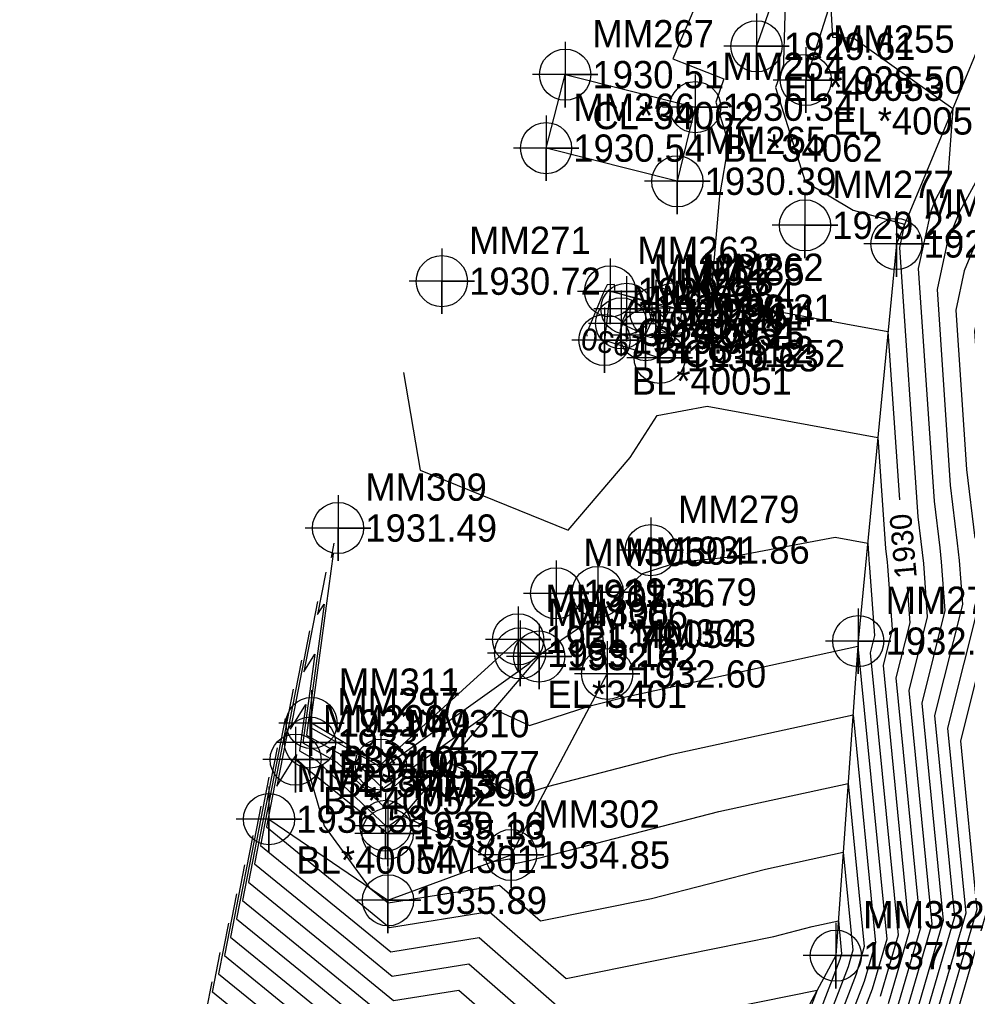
# Model space of a CAD drawing. Extents: x 1004378 to 1005103, y 553854 to 554288.
# Drawn here: x 1004892.9 to 1004979.8, y 554119.4 to 554208.9 of the extents above; entities that cross this region are included whole.
import ezdxf

# ---------------------------------------------------------------- set-up
doc = ezdxf.new("R2010")
doc.units = 0
for name, color, linetype in [('DTM Contours Major', 7, 'Continuous'), ('DTM Contours Major Text', 7, 'Continuous'), ('DTM Contours Minor', 7, 'Continuous'), ('Exist Building Cogo Elevation', 7, 'Continuous'), ('Exist Building Cogo Number', 7, 'Continuous'), ('Exist Building Cogo Point CELL', 7, 'Continuous'), ('Exist DTM Breakline', 7, 'Continuous'), ('Exist DTM Breakline Cogo Comment', 7, 'Continuous'), ('Exist DTM Breakline Cogo Elevation', 7, 'Continuous'), ('Exist DTM Breakline Cogo Number', 7, 'Continuous'), ('Exist DTM Breakline Cogo Point CELL', 7, 'Continuous'), ('Exist DTM Regular Point CELL', 7, 'Continuous'), ('Exist DTM Regular Point Cogo Elevation', 7, 'Continuous'), ('Exist DTM Regular Point Cogo Number', 7, 'Continuous'), ('Exist Other Culture Area Outline Cogo Comment', 7, 'Continuous'), ('Exist Other Culture Area Outline Cogo Elevation', 7, 'Continuous'), ('Exist Other Culture Area Outline Cogo Number', 7, 'Continuous'), ('Exist Other Culture Area Outline Cogo Point CELL', 7, 'Continuous'), ('Exist Structure Minor Drop Inlet Cogo Comment', 7, 'Continuous'), ('Exist Structure Minor Drop Inlet Cogo Elevation', 7, 'Continuous'), ('Exist Structure Minor Drop Inlet Cogo Number', 7, 'Continuous'), ('Exist Structure Minor Drop Inlet Cogo Point CELL', 7, 'Continuous')]:
    doc.layers.add(name, color=color, linetype=linetype)

msp = doc.modelspace()

# ---------------------------------------------------------------- linework, layer by layer
at = {"layer": 'DTM Contours Major'}
for points in [[(1004959.718, 554247.837), (1004956.604, 554227.189), (1004954.914, 554210.3), (1004952.827, 554205.351), (1004957.486, 554203.505), (1004956.747, 554201.367), (1004957.928, 554197.612), (1004957.091, 554192.78), (1004956.399, 554184.65), (1004957.552, 554183.351), (1004960.987, 554182.443), (1004972.543, 554180.34), (1004973.586, 554164.908)], [(1004988.055, 554197.353), (1004983.519, 554189.087), (1004981.07, 554183.147), (1004980.472, 554180.378), (1004981.231, 554169.159), (1004982.126, 554161.833), (1004982.368, 554159.624), (1004982.603, 554156.477), (1004979.182, 554142.834), (1004980.705, 554127.374), (1004976.99, 554114.65), (1004972.242, 554102.28), (1004972.017, 554101.096)], [(1004952.565, 554182.386), (1004951.57, 554182.721), (1004947.519, 554183.91), (1004947.453, 554184.657), (1004946.803, 554184.619), (1004946.533, 554184.06), (1004944.903, 554180.156), (1004944.942, 554179.927)], [(1004951.036, 554178.96), (1004952.198, 554181.759), (1004952.565, 554182.386)], [(1004974.291, 554156.941), (1004974.539, 554153.633), (1004973.275, 554148.595), (1004975.533, 554125.683), (1004973.303, 554118.045), (1004966.649, 554100.709), (1004964.833, 554091.127), (1004964.446, 554090.268), (1004962.705, 554079.148), (1004961.826, 554075.049), (1004962.449, 554069.829), (1004964.566, 554059.674), (1004964.614, 554059.515)], [(1004919.499, 554152.916), (1004917.744, 554143.914), (1004919.151, 554146.169), (1004918.574, 554141.908), (1004920.21, 554140.992), (1004926.611, 554134.921), (1004928.068, 554135.961), (1004934.459, 554132.981), (1004936.344, 554131.771), (1004937.836, 554132.01), (1004938.33, 554131.579), (1004939.667, 554131.849), (1004957.042, 554136.349), (1004968.89, 554138.926), (1004970.361, 554123.992), (1004969.616, 554121.44), (1004965.738, 554111.337)], [(1004915.782, 554139.515), (1004913.904, 554129.888), (1004921.295, 554123.861), (1004927.208, 554119.035), (1004933.185, 554119.992), (1004950.058, 554105.284), (1004959.128, 554107.116), (1004955.463, 554097.569), (1004955.218, 554096.276), (1004954.505, 554094.696), (1004954.285, 554093.293), (1004951.079, 554078.342), (1004951.712, 554073.035)], [(1004912.064, 554126.115), (1004911.158, 554121.47), (1004914.724, 554118.563), (1004927.833, 554107.862), (1004928.535, 554107.974), (1004932.097, 554104.869), (1004931.879, 554104.636), (1004950.839, 554094.361), (1004950.581, 554093.249), (1004946.204, 554080.072), (1004948.75, 554054.444), (1004948.799, 554054.036), (1004948.807, 554053.997), (1004948.82, 554053.955), (1004947.217, 554049.061)]]:
    msp.add_lwpolyline(points, dxfattribs=at)
at = {"layer": 'DTM Contours Minor'}
for points in [[(1004959.702, 554269.582), (1004971.624, 554262.617), (1004976.768, 554260.609), (1004978.047, 554251.242), (1004973.763, 554238.724), (1004972.987, 554236.396), (1004972.005, 554233.516), (1004967.53, 554219.799), (1004967.269, 554210.518), (1004967.445, 554207.322), (1004969.402, 554207.239), (1004978.487, 554200.785), (1004978.039, 554194.545), (1004976.925, 554192.516), (1004976.46, 554191.387), (1004975.325, 554186.125), (1004976.766, 554164.808), (1004977.29, 554160.519), (1004977.431, 554159.226), (1004977.764, 554154.77), (1004975.638, 554146.291), (1004977.602, 554126.359), (1004974.778, 554116.687)], [(1004960.573, 554259.577), (1004966.268, 554256.25), (1004968.726, 554255.291), (1004970.783, 554240.224), (1004971.304, 554236.409), (1004970.551, 554234.199), (1004963.15, 554211.518), (1004962.971, 554205.136), (1004962.961, 554204.794), (1004962.243, 554202.716), (1004964.954, 554194.096), (1004969.359, 554191.452), (1004974.072, 554190.188), (1004973.609, 554188.041), (1004975.278, 554163.357), (1004975.678, 554160.081), (1004975.786, 554159.093), (1004976.151, 554154.202), (1004974.457, 554147.443), (1004976.568, 554126.021), (1004974.041, 554117.366)], [(1004981.817, 554196.282), (1004979.123, 554191.373), (1004977.996, 554188.64), (1004977.041, 554184.209), (1004978.254, 554166.258), (1004978.902, 554160.957), (1004979.077, 554159.359), (1004979.377, 554155.339), (1004976.819, 554145.139), (1004978.636, 554126.697), (1004975.515, 554116.008)], [(1004981.321, 554190.23), (1004979.533, 554185.894), (1004978.757, 554182.294), (1004979.742, 554167.709), (1004980.514, 554161.395)], [(1004928.115, 554176.599), (1004929.652, 554167.649), (1004943.214, 554162.133), (1004948.917, 554168.804), (1004951.363, 554172.633), (1004955.952, 554173.497), (1004971.612, 554170.646), (1004972.301, 554160.456), (1004972.454, 554159.205), (1004972.495, 554158.827), (1004972.926, 554153.064), (1004972.094, 554149.748), (1004974.499, 554125.345), (1004972.566, 554118.724)], [(1004921.73, 554160.956), (1004921.473, 554159.639), (1004921.679, 554159.969), (1004919.527, 554144.092), (1004925.622, 554140.679), (1004926.081, 554140.244), (1004939.628, 554149.921), (1004940.424, 554150.661), (1004940.593, 554150.694), (1004940.925, 554150.961), (1004946.155, 554154.507), (1004950.035, 554158.171), (1004953.288, 554159.214), (1004958.115, 554159.697), (1004967.689, 554161.497), (1004970.681, 554160.953), (1004970.813, 554159.006), (1004970.842, 554158.767), (1004970.85, 554158.695), (1004971.313, 554152.495), (1004970.913, 554150.9), (1004973.465, 554125.006), (1004971.828, 554119.403)], [(1004920.986, 554158.276), (1004920.23, 554154.398), (1004920.837, 554155.369), (1004919.209, 554143.364), (1004923.818, 554140.783), (1004926.257, 554138.47), (1004936.437, 554145.741), (1004939.659, 554144.238), (1004945.239, 554146.033), (1004948.492, 554146.876), (1004969.785, 554151.508), (1004972.43, 554124.668), (1004971.091, 554120.082), (1004963.293, 554099.767)], [(1004980.99, 554155.908), (1004978, 554143.987), (1004979.671, 554127.036), (1004976.253, 554115.329)], [(1004920.243, 554155.596), (1004918.987, 554149.156), (1004919.994, 554150.769), (1004918.892, 554142.636), (1004922.014, 554140.888), (1004926.434, 554136.695), (1004932.252, 554140.851), (1004938.749, 554137.821), (1004941.311, 554138.645), (1004952.767, 554141.612), (1004969.338, 554145.217), (1004971.396, 554124.33), (1004970.354, 554120.761), (1004962.174, 554099.453)], [(1004918.756, 554150.236), (1004916.501, 554138.673), (1004918.309, 554141.569), (1004918.256, 554141.18), (1004918.406, 554141.096), (1004919.332, 554140.218), (1004920.835, 554135.037), (1004924.97, 554129.39), (1004926.552, 554128.1), (1004926.708, 554127.973), (1004936.906, 554129.606), (1004940.676, 554126.32), (1004950.867, 554128.379), (1004961.316, 554131.085), (1004968.442, 554132.635), (1004969.327, 554123.654), (1004968.879, 554122.119), (1004959.937, 554098.825)], [(1004918.012, 554147.556), (1004915.552, 554134.938), (1004925.238, 554127.04), (1004926.833, 554125.738), (1004935.976, 554127.202), (1004943.021, 554121.061), (1004962.068, 554124.909), (1004965.591, 554125.822), (1004967.994, 554126.344), (1004968.293, 554123.316), (1004968.142, 554122.798), (1004958.819, 554098.511)], [(1004917.269, 554144.876), (1004915.002, 554133.254), (1004923.924, 554125.981), (1004926.958, 554123.504), (1004935.046, 554124.799), (1004945.367, 554115.802), (1004966.063, 554119.983), (1004957.7, 554098.197)], [(1004916.525, 554142.195), (1004914.453, 554131.571), (1004922.609, 554124.921), (1004927.083, 554121.269), (1004934.115, 554122.395), (1004947.713, 554110.543)], [(1004915.038, 554136.835), (1004913.355, 554128.204), (1004919.981, 554122.802), (1004927.333, 554116.8)], [(1004914.295, 554134.155), (1004912.806, 554126.521), (1004918.667, 554121.742), (1004927.458, 554114.566)], [(1004913.551, 554131.475), (1004912.257, 554124.837), (1004917.352, 554120.683), (1004927.583, 554112.331)], [(1004912.808, 554128.795), (1004911.707, 554123.154), (1004916.038, 554119.623), (1004927.708, 554110.097)], [(1004981.739, 554127.712), (1004977.727, 554113.971)], [(1004892.909, 553980.228), (1004909.736, 553977.519), (1004919.988, 553982.517), (1004925.173, 553984.426), (1004936.898, 553999.835), (1004937.254, 554000.219), (1004937.418, 554000.896), (1004939.715, 554013.407), (1004939.746, 554016.607), (1004940.982, 554023.681), (1004941.12, 554046.622), (1004942.146, 554051.575), (1004941.271, 554057.545), (1004943.194, 554079.367), (1004940.844, 554083.886), (1004927.509, 554103.798), (1004927.675, 554104.761), (1004926.297, 554106.983), (1004913.409, 554117.504), (1004910.609, 554119.787), (1004911.321, 554123.435)], [(1004896.871, 553987.94), (1004907.319, 553986.258), (1004918.577, 553991.746), (1004920.602, 553996.072), (1004926.171, 554004.786), (1004927.401, 554011.483), (1004927.417, 554013.109), (1004930.834, 554032.674), (1004930.895, 554042.816), (1004933.912, 554057.37), (1004933.33, 554061.338), (1004934.608, 554075.845), (1004923.665, 554096.889), (1004921.296, 554100.426), (1004922.463, 554107.183), (1004921.461, 554108.798), (1004912.095, 554116.444), (1004910.06, 554118.103), (1004910.577, 554120.754)]]:
    msp.add_lwpolyline(points, dxfattribs=at)
at = {"layer": 'Exist Building Cogo Point CELL'}
for points in [[(1004938.808, 554153.855), (1004938.808, 554147.855), (1004938.808, 554150.855), (1004941.808, 554150.855), (1004935.808, 554150.855)], [(1004919.543, 554145.67), (1004919.543, 554139.67), (1004919.543, 554142.67), (1004922.543, 554142.67), (1004916.543, 554142.67)], [(1004926.468, 554138.051), (1004926.468, 554132.051), (1004926.468, 554135.051), (1004929.468, 554135.051), (1004923.468, 554135.051)]]:
    msp.add_lwpolyline(points, dxfattribs=at)
for centre in [(1004938.808, 554150.855), (1004919.543, 554142.67), (1004926.468, 554135.051)]:
    msp.add_circle(centre, 2.344, dxfattribs=at)
at = {"layer": 'Exist DTM Breakline'}
for points in [[(1004977.38, 554270.285), (1004987.161, 554267.094), (1004974.231, 554232.47), (1004965.01, 554203.394)], [(1004977.332, 554269.403), (1004984.686, 554265.845), (1004970.343, 554234.297), (1004960.488, 554206.483)], [(1004999.282, 554239.926), (1004986.87, 554220.91), (1004973.315, 554188.37), (1004969.818, 554151.968), (1004967.766, 554123.144), (1004953.718, 554097.079)], [(1004954.867, 554200.906), (1004953.225, 554194.112), (1004941.19, 554197.154), (1004942.942, 554203.89), (1004954.867, 554200.906)], [(1004946.549, 554179.56), (1004951.61, 554177.935), (1004952.995, 554182.485), (1004947.068, 554184.027), (1004946.549, 554179.56)], [(1004915.784, 554135.651), (1004926.694, 554128.215), (1004937.976, 554132.372), (1004946.796, 554148.963), (1004945.928, 554156.47), (1004942.107, 554156.345)], [(1004918.224, 554141.107), (1004926.67, 554134.328), (1004940.555, 554150.554), (1004938.629, 554152.129), (1004926.04, 554140.655), (1004919.688, 554144.461)]]:
    msp.add_lwpolyline(points, dxfattribs=at)
msp.add_lwpolyline([(1004948.079, 554181.091), (1004950.3, 554180.028), (1004951.243, 554182.08), (1004949.022, 554183.143)], close=True, dxfattribs=at)
at = {"layer": 'Exist DTM Breakline Cogo Point CELL'}
for points in [[(1004960.488, 554209.483), (1004960.488, 554203.483), (1004960.488, 554206.483), (1004963.488, 554206.483), (1004957.488, 554206.483)], [(1004965.01, 554206.394), (1004965.01, 554200.394), (1004965.01, 554203.394), (1004968.01, 554203.394), (1004962.01, 554203.394)], [(1004973.315, 554191.37), (1004973.315, 554185.37), (1004973.315, 554188.37), (1004976.315, 554188.37), (1004970.315, 554188.37)], [(1004947.068, 554187.027), (1004947.068, 554181.027), (1004947.068, 554184.027), (1004950.068, 554184.027), (1004944.068, 554184.027)], [(1004952.995, 554185.485), (1004952.995, 554179.485), (1004952.995, 554182.485), (1004955.995, 554182.485), (1004949.995, 554182.485)], [(1004946.549, 554182.56), (1004946.549, 554176.56), (1004946.549, 554179.56), (1004949.549, 554179.56), (1004943.549, 554179.56)], [(1004951.61, 554180.935), (1004951.61, 554174.935), (1004951.61, 554177.935), (1004954.61, 554177.935), (1004948.61, 554177.935)], [(1004942.107, 554159.345), (1004942.107, 554153.345), (1004942.107, 554156.345), (1004945.107, 554156.345), (1004939.107, 554156.345)], [(1004945.928, 554159.47), (1004945.928, 554153.47), (1004945.928, 554156.47), (1004948.928, 554156.47), (1004942.928, 554156.47)], [(1004938.629, 554155.129), (1004938.629, 554149.129), (1004938.629, 554152.129), (1004941.629, 554152.129), (1004935.629, 554152.129)], [(1004969.818, 554154.968), (1004969.818, 554148.968), (1004969.818, 554151.968), (1004972.818, 554151.968), (1004966.818, 554151.968)], [(1004940.555, 554153.554), (1004940.555, 554147.554), (1004940.555, 554150.554), (1004943.555, 554150.554), (1004937.555, 554150.554)], [(1004946.796, 554151.963), (1004946.796, 554145.963), (1004946.796, 554148.963), (1004949.796, 554148.963), (1004943.796, 554148.963)], [(1004919.688, 554147.461), (1004919.688, 554141.461), (1004919.688, 554144.461), (1004922.688, 554144.461), (1004916.688, 554144.461)], [(1004918.224, 554144.107), (1004918.224, 554138.107), (1004918.224, 554141.107), (1004921.224, 554141.107), (1004915.224, 554141.107)], [(1004926.04, 554143.655), (1004926.04, 554137.655), (1004926.04, 554140.655), (1004929.04, 554140.655), (1004923.04, 554140.655)], [(1004915.784, 554138.651), (1004915.784, 554132.651), (1004915.784, 554135.651), (1004918.784, 554135.651), (1004912.784, 554135.651)], [(1004926.67, 554137.328), (1004926.67, 554131.328), (1004926.67, 554134.328), (1004929.67, 554134.328), (1004923.67, 554134.328)], [(1004937.976, 554135.372), (1004937.976, 554129.372), (1004937.976, 554132.372), (1004940.976, 554132.372), (1004934.976, 554132.372)], [(1004926.694, 554131.215), (1004926.694, 554125.215), (1004926.694, 554128.215), (1004929.694, 554128.215), (1004923.694, 554128.215)], [(1004967.766, 554126.144), (1004967.766, 554120.144), (1004967.766, 554123.144), (1004970.766, 554123.144), (1004964.766, 554123.144)]]:
    msp.add_lwpolyline(points, dxfattribs=at)
for centre in [(1004960.488, 554206.483), (1004965.01, 554203.394), (1004973.315, 554188.37), (1004947.068, 554184.027), (1004952.995, 554182.485), (1004946.549, 554179.56), (1004951.61, 554177.935), (1004942.107, 554156.345), (1004945.928, 554156.47), (1004938.629, 554152.129), (1004969.818, 554151.968), (1004940.555, 554150.554), (1004946.796, 554148.963), (1004919.688, 554144.461), (1004918.224, 554141.107), (1004926.04, 554140.655), (1004915.784, 554135.651), (1004926.67, 554134.328), (1004937.976, 554132.372), (1004926.694, 554128.215), (1004967.766, 554123.144)]:
    msp.add_circle(centre, 2.344, dxfattribs=at)
at = {"layer": 'Exist DTM Regular Point CELL'}
for points in [[(1004964.93, 554193.077), (1004964.93, 554187.077), (1004964.93, 554190.077), (1004967.93, 554190.077), (1004961.93, 554190.077)], [(1004931.633, 554187.958), (1004931.633, 554181.958), (1004931.633, 554184.958), (1004934.633, 554184.958), (1004928.633, 554184.958)], [(1004922.112, 554165.334), (1004922.112, 554159.334), (1004922.112, 554162.334), (1004925.112, 554162.334), (1004919.112, 554162.334)], [(1004950.787, 554163.31), (1004950.787, 554157.31), (1004950.787, 554160.31), (1004953.787, 554160.31), (1004947.787, 554160.31)]]:
    msp.add_lwpolyline(points, dxfattribs=at)
for centre in [(1004964.93, 554190.077), (1004931.633, 554184.958), (1004922.112, 554162.334), (1004950.787, 554160.31)]:
    msp.add_circle(centre, 2.344, dxfattribs=at)
at = {"layer": 'Exist Other Culture Area Outline Cogo Point CELL'}
for points in [[(1004942.942, 554206.89), (1004942.942, 554200.89), (1004942.942, 554203.89), (1004945.942, 554203.89), (1004939.942, 554203.89)], [(1004954.867, 554203.906), (1004954.867, 554197.906), (1004954.867, 554200.906), (1004957.867, 554200.906), (1004951.867, 554200.906)], [(1004941.19, 554200.154), (1004941.19, 554194.154), (1004941.19, 554197.154), (1004944.19, 554197.154), (1004938.19, 554197.154)], [(1004953.225, 554197.112), (1004953.225, 554191.112), (1004953.225, 554194.112), (1004956.225, 554194.112), (1004950.225, 554194.112)]]:
    msp.add_lwpolyline(points, dxfattribs=at)
for centre in [(1004942.942, 554203.89), (1004954.867, 554200.906), (1004941.19, 554197.154), (1004953.225, 554194.112)]:
    msp.add_circle(centre, 2.344, dxfattribs=at)
at = {"layer": 'Exist Structure Minor Drop Inlet Cogo Point CELL'}
for points in [[(1004948.569, 554185.432), (1004948.569, 554179.432), (1004948.569, 554182.432), (1004951.569, 554182.432), (1004945.569, 554182.432)], [(1004951.243, 554185.08), (1004951.243, 554179.08), (1004951.243, 554182.08), (1004954.243, 554182.08), (1004948.243, 554182.08)], [(1004948.079, 554184.091), (1004948.079, 554178.091), (1004948.079, 554181.091), (1004951.079, 554181.091), (1004945.079, 554181.091)], [(1004950.322, 554183.017), (1004950.322, 554177.017), (1004950.322, 554180.017), (1004953.322, 554180.017), (1004947.322, 554180.017)]]:
    msp.add_lwpolyline(points, dxfattribs=at)
for centre in [(1004948.569, 554182.432), (1004951.243, 554182.08), (1004948.079, 554181.091), (1004950.322, 554180.017)]:
    msp.add_circle(centre, 2.344, dxfattribs=at)

# ---------------------------------------------------------------- texts
at = {"layer": 'DTM Contours Major Text'}
for rotation, p in [(170.98158, (1004950.475, 554179.787)), (95.05741, (1004975.19, 554157.802))]:
    msp.add_text('1930', height=2, rotation=rotation, dxfattribs=at).set_placement(p)
at = {"layer": 'Exist Building Cogo Elevation'}
for s, p in [('1939.14', (1004941.308, 554149.605)), ('EL*3401', (1004941.308, 554145.855)), ('1933.74', (1004922.043, 554141.42)), ('BL*34013', (1004922.043, 554137.67)), ('1939.16', (1004928.968, 554133.801))]:
    msp.add_text(s, height=2.5, dxfattribs=at).set_placement(p)
at = {"layer": 'Exist Building Cogo Number'}
for s, p in [('MM308', (1004941.308, 554153.355)), ('MM297', (1004922.043, 554145.17)), ('MM300', (1004928.968, 554137.551))]:
    msp.add_text(s, height=2.5, dxfattribs=at).set_placement(p)
at = {"layer": 'Exist DTM Breakline Cogo Comment'}
for s, p in [('EL*40053', (1004962.988, 554201.483)), ('EL*40051', (1004967.51, 554198.394)), ('CL*40051', (1004949.568, 554179.027)), ('BL*40051', (1004949.049, 554174.56)), ('EL*40054', (1004944.607, 554151.345)), ('EL*40052', (1004922.188, 554139.461)), ('BL*40052', (1004920.724, 554136.107)), ('BL*40054', (1004918.284, 554130.651))]:
    msp.add_text(s, height=2.5, dxfattribs=at).set_placement(p)
at = {"layer": 'Exist DTM Breakline Cogo Elevation'}
for s, p in [('1929.61', (1004962.988, 554205.233)), ('1928.50', (1004967.51, 554202.144)), ('1929.17', (1004975.815, 554187.12)), ('1929.97', (1004949.568, 554182.777)), ('1930.31', (1004955.495, 554181.235)), ('1929.91', (1004949.049, 554178.31)), ('1930.63', (1004954.11, 554176.685)), ('1931.36', (1004944.607, 554155.095)), ('1931.79', (1004948.428, 554155.22)), ('1931.78', (1004941.129, 554150.879)), ('1932.93', (1004972.318, 554150.718)), ('1932.02', (1004943.055, 554149.304)), ('1932.60', (1004949.296, 554147.713)), ('1931.49', (1004922.188, 554143.211)), ('1936.10', (1004920.724, 554139.857)), ('1931.77', (1004928.54, 554139.405)), ('1936.58', (1004918.284, 554134.401)), ('1935.33', (1004929.17, 554133.078)), ('1934.85', (1004940.476, 554131.122)), ('1935.89', (1004929.194, 554126.965)), ('1937.51', (1004970.266, 554121.894))]:
    msp.add_text(s, height=2.5, dxfattribs=at).set_placement(p)
at = {"layer": 'Exist DTM Breakline Cogo Number'}
for s, p in [('MM255', (1004967.51, 554205.894)), ('MM276', (1004975.815, 554190.87)), ('MM263', (1004949.568, 554186.527)), ('MM262', (1004955.495, 554184.985)), ('MM260', (1004949.049, 554182.06)), ('MM261', (1004954.11, 554180.435)), ('MM305', (1004944.607, 554158.845)), ('MM304', (1004948.428, 554158.97)), ('MM307', (1004941.129, 554154.629)), ('MM278', (1004972.318, 554154.468)), ('MM306', (1004943.055, 554153.054)), ('MM303', (1004949.296, 554151.463)), ('MM311', (1004922.188, 554146.961)), ('MM296', (1004920.724, 554143.607)), ('MM310', (1004928.54, 554143.155)), ('MM298', (1004918.284, 554138.151)), ('MM299', (1004929.17, 554136.828)), ('MM302', (1004940.476, 554134.872)), ('MM301', (1004929.194, 554130.715)), ('MM332', (1004970.266, 554125.644))]:
    msp.add_text(s, height=2.5, dxfattribs=at).set_placement(p)
at = {"layer": 'Exist DTM Regular Point Cogo Elevation'}
for s, p in [('1929.22', (1004967.43, 554188.827)), ('1930.72', (1004934.133, 554183.708)), ('1931.49', (1004924.612, 554161.084)), ('1931.86', (1004953.287, 554159.06))]:
    msp.add_text(s, height=2.5, dxfattribs=at).set_placement(p)
at = {"layer": 'Exist DTM Regular Point Cogo Number'}
for s, p in [('MM277', (1004967.43, 554192.577)), ('MM271', (1004934.133, 554187.458)), ('MM309', (1004924.612, 554164.834)), ('MM279', (1004953.287, 554162.81))]:
    msp.add_text(s, height=2.5, dxfattribs=at).set_placement(p)
at = {"layer": 'Exist Other Culture Area Outline Cogo Comment'}
for s, p in [('CL*34062', (1004945.442, 554198.89)), ('BL*34062', (1004957.367, 554195.906))]:
    msp.add_text(s, height=2.5, dxfattribs=at).set_placement(p)
at = {"layer": 'Exist Other Culture Area Outline Cogo Elevation'}
for s, p in [('1930.51', (1004945.442, 554202.64)), ('1930.34', (1004957.367, 554199.656)), ('1930.54', (1004943.69, 554195.904)), ('1930.39', (1004955.725, 554192.862))]:
    msp.add_text(s, height=2.5, dxfattribs=at).set_placement(p)
at = {"layer": 'Exist Other Culture Area Outline Cogo Number'}
for s, p in [('MM267', (1004945.442, 554206.39)), ('MM264', (1004957.367, 554203.406)), ('MM266', (1004943.69, 554199.654)), ('MM265', (1004955.725, 554196.612))]:
    msp.add_text(s, height=2.5, dxfattribs=at).set_placement(p)
at = {"layer": 'Exist Structure Minor Drop Inlet Cogo Comment'}
for s, p in [('BL*31252', (1004951.069, 554177.432)), ('CL*31252', (1004953.743, 554177.08))]:
    msp.add_text(s, height=2.5, dxfattribs=at).set_placement(p)
at = {"layer": 'Exist Structure Minor Drop Inlet Cogo Elevation'}
for s, p in [('1929.26', (1004951.069, 554181.182)), ('1929.04', (1004953.743, 554180.83)), ('1929.66', (1004950.579, 554179.841)), ('1929.25', (1004952.822, 554178.767))]:
    msp.add_text(s, height=2.5, dxfattribs=at).set_placement(p)
at = {"layer": 'Exist Structure Minor Drop Inlet Cogo Number'}
for s, p in [('MM282', (1004951.069, 554184.932)), ('MM285', (1004953.743, 554184.58)), ('MM283', (1004950.579, 554183.591)), ('MM284', (1004952.822, 554182.517))]:
    msp.add_text(s, height=2.5, dxfattribs=at).set_placement(p)

doc.saveas('drawing.dxf')
